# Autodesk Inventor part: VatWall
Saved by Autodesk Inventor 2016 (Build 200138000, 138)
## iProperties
Created: 2015-11
Part Number: VatWall
Material: Generic
Document SubType Name: Modeling
Designer: John
Density: 1 g/cm^3
Appearance: Default
Author: John
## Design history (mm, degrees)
feature "Base1"
body "Solid1"
